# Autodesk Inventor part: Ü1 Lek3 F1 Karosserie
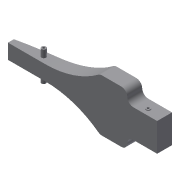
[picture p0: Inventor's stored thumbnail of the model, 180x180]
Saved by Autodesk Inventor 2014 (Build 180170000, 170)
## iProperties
Created: 2013-07
Part Number: Ü1 Lek3 F1 Karosserie
Material: Generisch
Document SubType Name: Modeling
Designer: Sofia
Density: 1 g/cm^3
Appearance: Vorgabe
Author: Sofia
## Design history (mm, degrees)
sketch "Skizze1"
  geometry: L1 (0, 0)-(200, 0); L2 (200, 0)-(200, 20); L3 (200, 20)-(110, 20); L4 (0, 8)-(0, 0); A1 r 510.167 centre (110, -490.167) between (110, 20) and (0, 8)
  constraints: 8 end point, 2 perpendicular, 2 point on circle, 1 centre point, 1 horizontal, 1 parallel, 1 tangent
  dimensions: "d2" = 200 distance of L1.start L1.end; "d3" = 20 distance of L1.end L2.end; "d4" = 90 distance of L2.end L3.end; "d5" = 8 distance of L4.start L1.start
extrude "Extrusion1" new body sketch "Skizze1" distance "d6" = 35; taper "d7" = 0 deg
sketch "Skizze2"
  geometry: L1 (0, 0)-(200, 0) reference; L2 (0, 35)-(200, 35) reference; L3 (0, 0)-(0, 35) reference; L4 (0, 10)-(50, 10); L5 (200, 35)-(160, 35); L6 (160, 35)-(160, 19); L7 (160, 19)-(200, 19); L8 (200, 19)-(200, 35); A1 r 120 centre (50, 130) between (50, 10) and (123.314, 35)
  constraints: 10 end point, 2 parallel, 2 perpendicular, 2 point on circle, 2 point on line, 1 centre point, 1 horizontal, 1 tangent
  dimensions: "d8" = 50 distance of L4.start L4.end; "d9" = 10 distance between parallel lines of L4 L1; "d10" = 120 radius of A1; "d13" = 40 distance of L7.end L6.end; "d14" = 16 distance of L6.end L5.end
extrude "Extrusion2" cut sketch "Skizze2" stored distance "d15" = 35; taper "d16" = 0 deg
sketch "Skizze3"
  geometry: L1 (0, 0)-(0, 8) reference; L2 (50, 0)-(0, 0) reference; C1 r 3 at (40, 8)
  constraints: 1 centre point
  dimensions: "d17" = 6 diameter of C1; "d18" = 8 distance from line of C1.centre L2; "d19" = 40 distance from line of C1.centre L1
extrude "Extrusion3" join sketch "Skizze3" distance "d20" = 10; taper "d21" = 0 deg
hole "Bohrung1" diameter "d24" = 3; stored, may be unused: countersink angle "d28" = 90 deg, drill point angle "d30" = 118 deg; dims "d22" = 10, "d23" = 10, "d25" = 6, "d26" = 4, "d27" = 2, "d29" = 8
pattern_linear "Rechteckige Anordnung1"
fillet "Rundung1" dims "d34" = 8
mirror "Spiegeln1"
node "Volumenkörper1"
